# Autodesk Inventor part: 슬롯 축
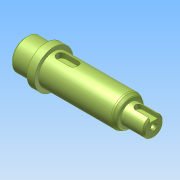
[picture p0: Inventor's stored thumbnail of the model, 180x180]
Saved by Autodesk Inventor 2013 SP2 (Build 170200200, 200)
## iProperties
Created: 2025-09
Part Number: 슬롯 축
Material: Generic
Document SubType Name: Modeling
Designer: a
Density: 1 g/cm^3
Author: a
변환 표준: STEP AP214IS
전처리기: Build: 200, Release: 2013 SP2 Update 6 - Date: Thu 07/17/2014
전송 단위: 밀리미터
불확실성: 0.01
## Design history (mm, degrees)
node "슬롯 축1"
node "솔리드1"
node "기준1"
